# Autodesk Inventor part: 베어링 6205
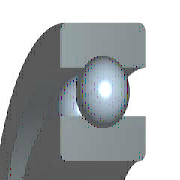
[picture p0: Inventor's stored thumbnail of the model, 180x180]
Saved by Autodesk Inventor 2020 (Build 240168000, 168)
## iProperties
Created: 2015-10
Part Number: 베어링 6205
Material: 강, 연강
Description: 깊은 그루브 볼 베어링
Document SubType Name: Modeling
Standard: KS B 2023
Designer: mdu
Standards Organization: KS
Language: ko-KR
Size Designation: 6205 - 25 x 52 x 15
Categories: <MemberInstance><Categories><Category DisplayName="샤프트 부품" InternalName="7f7aeb1f-a693-4053-b835-cee3144e0d98" Mnemonic="SHFT"><Category DisplayName="베어링" Inter
Density: 1 g/cm^3
Appearance: 노란색
IsCustomPart: 1
Author: mdu
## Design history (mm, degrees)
sketch "스케치" dims "d0" = 7.02 (= -0.26 x WD + 0.26 x BD)
  geometry: L1 (3.99, 19.25)-(11.01, 19.25); L2 (7.5, 19.25)-(7.5, 15.74); L3 (7.5, 19.25)-(7.5, 22.76); L4 (4.892, 16.901)-(0, 16.901); L5 (0, 12.5)-(15, 12.5); L6 (4.892, 21.599)-(0, 21.599); L7 (0, 26)-(15, 26); L8 (15, 12.5)-(15, 16.901); L9 (10.108, 16.901)-(15, 16.901); L10 (10.108, 21.599)-(15, 21.599); L11 (15, 26)-(15, 21.599); L12 (-1.4, 0)-(8.4, 0) reference; L13 (0, -0.3)-(0, 5.3) reference
  constraints: 22 end point, 4 point on line, 2 collinear, 2 perpendicular, 2 symmetric about line, 1 midpoint, 1 parallel, 14 other
  dimensions: "d9" = 25 diameter of L5 L12 (= WD); "d11" = 52 diameter of L7 L12 (= BD); "d12" = 15 distance between parallel lines of L8 L13 (= KB); "d13" = 33.802 diameter of L9 L12 (= 0.326 x BD + 0.674 x WD)
revolve "본체" stored, may be unused: angle "d6" = 90 deg
revolve "볼" stored, may be unused: angle "d7" = 90 deg
pattern_circular "IDS_ARRAYBALL[SIMPL:T]" dims angle "d3" = 360 deg
body "Solid1"
fillet "모깎기1" dims "d1" = 1 (= KRS)
other parameters: "WD" = 25 [user parameter; used in 5 equation terms], "BD" = 52 [user parameter; used in 5 equation terms], "KB" = 15 [user parameter; used in 1 equation term], "KRS" = 1 [user parameter; used in 1 equation term], "d4" = 0, "d5" = 0, "d8" = 0, "d14" = 0, "d15" = 0, "BBA" = 0 [user parameter], "BC0" = 7800000 [user parameter], "BC" = 1.4e+07 [user parameter], "BR" = 26 (= 0.5 x BD) [user parameter], "WR" = 12.5 (= 0.5 x WD) [user parameter]
